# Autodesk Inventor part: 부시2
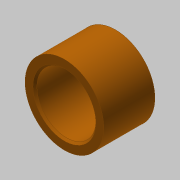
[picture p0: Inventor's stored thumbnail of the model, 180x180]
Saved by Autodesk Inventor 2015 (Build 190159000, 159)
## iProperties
Created: 2016-08
Part Number: 부시2
Material: 강철, 탄소
Document SubType Name: Modeling
Designer: mduedu
Density: 7.87 g/cm^3
Appearance: 주황색
Author: mduedu
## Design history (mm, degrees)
sketch "스케치1"
  geometry: C1 r 7.5 at (0, 0); C2 r 10 at (0, 0); 1 further point
  constraints: 2 centre point, 2 coincident
  dimensions: "d0" = 15 diameter of C1; "d1" = 20 diameter of C2
extrude "돌출1" new body sketch "스케치1" stored distance "d2" = 13; taper "d3" = 0 deg
chamfer "모따기1" distance "d4" = 0.5; stored, may be unused: second distance "d5" = 2, angle "d6" = 45 deg
node "솔리드1"
